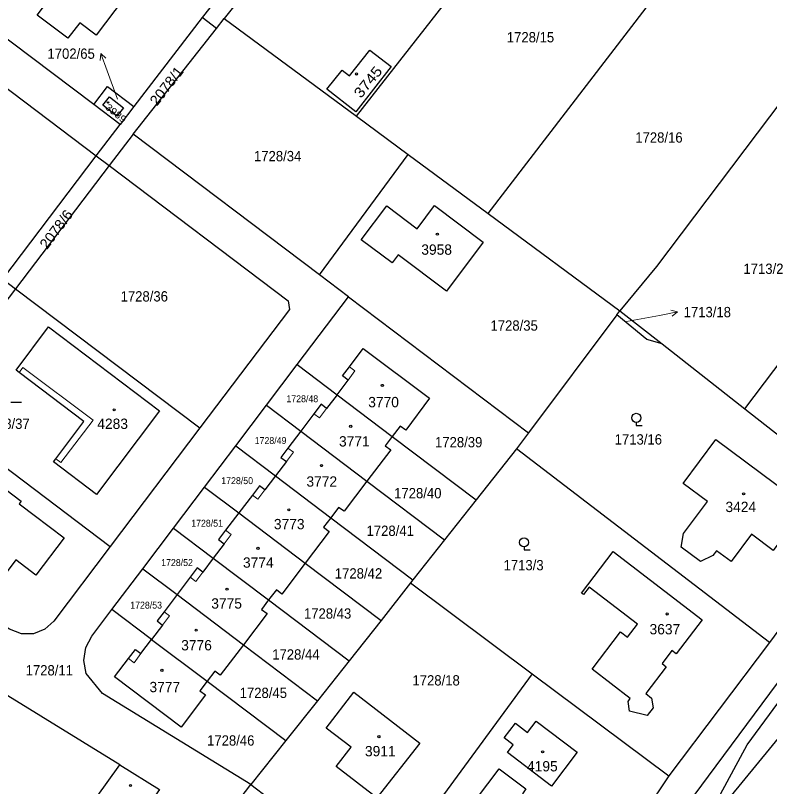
# Model space of a CAD drawing. Extents: x -679733 to -673243, y -1075091 to -1066557.
# Drawn here: x -677106.6 to -676982.3, y -1072174.7 to -1072047.5 of the extents above; entities that cross this region are included whole.
import ezdxf
from ezdxf.enums import TextEntityAlignment as Align

# ---------------------------------------------------------------- set-up
doc = ezdxf.new("R2010")
doc.units = 0
doc.header["$LTSCALE"] = 0.68
for name, color, linetype, lineweight in [('1', 7, 'Continuous', 25), ('3', 7, 'Continuous', 25), ('4', 7, 'Continuous', 13), ('5', 7, 'Continuous', 25), ('7', 7, 'Continuous', 13)]:
    doc.layers.add(name, color=color, linetype=linetype, lineweight=lineweight)
doc.layers.add('2', color=7, linetype='Continuous')

msp = doc.modelspace()

# ---------------------------------------------------------------- linework, layer by layer
at = {"layer": '1'}
for p, q in [((-677074.58, -1072046.3), (-677075.82, -1072047.9)), ((-677073.48, -1072049.71), (-677072.18, -1072048.07)), ((-677093.28, -1072070.69), (-677091.14, -1072072.31)), ((-677056.5, -1072090.33), (-677041.85, -1072070.46)), ((-677028.68, -1072080.19), (-677006.95, -1072096.23)), ((-677108.7, -1072091), (-677106.59, -1072092.6)), ((-677051.71, -1072093.95), (-677022.03, -1072116.37)), ((-677007.46, -1072096.91), (-677006.95, -1072096.23)), ((-677006.95, -1072096.23), (-677000, -1072101.69)), ((-677060.16, -1072105.11), (-677053.59, -1072110.07)), ((-677053.59, -1072110.07), (-677044.48, -1072116.96)), ((-677065.22, -1072111.81), (-677059.57, -1072116.08)), ((-676986.37, -1072112.39), (-676965.77, -1072128.57)), ((-677059.57, -1072116.08), (-677048.65, -1072124.33)), ((-677044.48, -1072116.96), (-677030.64, -1072127.41)), ((-677070.29, -1072118.51), (-677063.73, -1072123.47)), ((-677048.65, -1072124.33), (-677035.85, -1072134)), ((-677075.42, -1072125.29), (-677069.77, -1072129.56)), ((-677069.77, -1072129.56), (-677058.83, -1072137.82)), ((-677054.62, -1072130.36), (-677041.06, -1072140.6)), ((-677080.55, -1072132.07), (-677073.99, -1072137.02)), ((-677073.99, -1072137.02), (-677064.87, -1072143.91)), ((-677085.62, -1072138.77), (-677079.97, -1072143.03)), ((-677084.15, -1072150.41), (-677090.69, -1072145.47)), ((-677084.15, -1072150.41), (-677075.01, -1072157.31)), ((-677069.03, -1072151.3), (-677056.82, -1072160.52)), ((-677021.42, -1072156.06), (-677046.63, -1072190.51)), ((-677089.42, -1072171.09), (-677082.85, -1072175.14))]:
    msp.add_line(p, q, dxfattribs=at)
for points in [[(-677017.03, -1072021.51), (-677038.79, -1072006.32), (-677072.18, -1072048.07), (-677050.4, -1072064.16)], [(-677097.95, -1072051.28), (-677103.02, -1072047.53), (-677101.13, -1072044.95), (-677103.7, -1072043.07), (-677097.58, -1072034.86), (-677087.13, -1072042.64), (-677093.28, -1072050.82), (-677096, -1072048.77)], [(-677048.19, -1072053.29), (-677044.66, -1072055.95), (-677050.49, -1072063.44), (-677055.26, -1072059.73), (-677052.75, -1072056.56), (-677051.54, -1072057.51)], [(-677088.8, -1072062.76), (-677089.88, -1072064.14), (-677092.18, -1072062.32), (-677091.11, -1072060.96)], [(-677045.39, -1072078.94), (-677040.4, -1072082.71), (-677037.54, -1072078.89), (-677029.5, -1072084.92), (-677035.55, -1072092.98), (-677043.51, -1072087.01), (-677044.5, -1072088.35), (-677049.58, -1072084.54)], [(-677106, -1072106.42), (-677106.51, -1072106.03), (-677101.15, -1072098.9), (-677082.84, -1072112.73), (-677093.22, -1072126.53), (-677100.34, -1072121.12), (-677099.95, -1072120.62), (-677095.34, -1072114.51)], [(-676991.02, -1072135.79), (-676991.65, -1072136.57), (-676993.63, -1072137.58), (-676996.84, -1072135.18), (-676996.46, -1072132.95), (-676992.52, -1072127.67), (-676996.51, -1072124.7), (-676991.14, -1072117.47), (-676976.27, -1072128.51), (-676981.66, -1072135.77), (-676985.27, -1072133.08), (-676988.61, -1072137.57)], [(-677117.05, -1072129.2), (-677112.13, -1072122.73), (-677105.66, -1072127.62), (-677106, -1072128.08), (-677098.59, -1072133.68), (-677103.25, -1072139.81), (-677106.53, -1072137.27), (-677109.37, -1072141), (-677112.1, -1072138.93), (-677112.28, -1072139.16), (-677114.97, -1072137.06), (-677114.8, -1072136.83), (-677117.35, -1072134.96), (-677119.89, -1072133.07)], [(-677002.69, -1072159.33), (-677001.72, -1072160.09), (-677001.48, -1072161.67), (-677002.44, -1072162.96), (-677005.38, -1072162.26), (-677005.56, -1072160.64), (-677005.25, -1072160.16), (-677011.53, -1072155.33), (-677006.85, -1072149.18), (-677005.68, -1072150.05), (-677004.06, -1072147.9), (-677012.04, -1072141.82), (-677012.95, -1072143.02), (-677013.28, -1072142.78), (-677008.04, -1072135.92), (-676993.39, -1072147.17), (-676997.65, -1072152.79), (-676998.37, -1072152.26), (-676999.99, -1072154.4), (-676999.31, -1072154.94)], [(-677047.03, -1072176.53), (-677053.73, -1072171.35), (-677051.28, -1072168.19), (-677055.37, -1072165.02), (-677050.84, -1072159.13), (-677039.96, -1072167.5)], [(-677014.01, -1072169.02), (-677018.21, -1072174.6), (-677025.47, -1072169.08), (-677024.53, -1072167.77), (-677026.01, -1072166.65), (-677024.16, -1072164.22), (-677022.19, -1072165.76), (-677020.75, -1072163.91)], [(-677022.43, -1072175.06), (-677023.03, -1072175.85), (-677013.34, -1072183.15), (-677017.74, -1072189.03), (-677020.94, -1072186.65), (-677024.75, -1072191.65), (-677029.79, -1072187.85), (-677030, -1072188.09), (-677035.87, -1072183.69), (-677026.86, -1072171.73)]]:
    msp.add_lwpolyline(points, close=True, dxfattribs=at)
for points in [[(-677050.4, -1072064.16), (-677041.85, -1072070.46), (-677028.68, -1072080.19), (-676995.7, -1072037.23), (-677017.03, -1072021.51)], [(-677143.01, -1072065.09), (-677128.23, -1072045.55), (-677126.83, -1072045.35), (-677093.28, -1072070.69), (-677089.36, -1072065.52), (-677093.71, -1072062.23), (-677124.11, -1072039.27), (-677128.9, -1072035.65), (-677137.65, -1072047.21), (-677142.72, -1072053.91), (-677147.79, -1072060.61), (-677152.92, -1072067.39), (-677158.04, -1072074.17)], [(-677075.82, -1072047.9), (-677087.1, -1072062.55), (-677089.36, -1072065.52)], [(-677087.2, -1072067.14), (-677073.48, -1072049.71), (-677075.82, -1072047.9)], [(-677003.56, -1072188.05), (-676937.07, -1072098.47), (-676924.77, -1072082.25), (-676901.08, -1072050.53), (-676900.33, -1072051.15)], [(-676973.98, -1072053.28), (-677000.89, -1072088.91), (-677006.95, -1072096.23)], [(-677093.71, -1072062.23), (-677091.45, -1072059.24), (-677087.1, -1072062.55)], [(-677143.01, -1072065.09), (-677108.7, -1072091), (-677093.28, -1072070.69)], [(-677067.77, -1072174.34), (-677092.23, -1072159.33), (-677094.94, -1072156.01), (-677095.33, -1072153.89), (-677095.01, -1072151.77), (-677094.01, -1072149.86), (-677090.69, -1072145.47), (-677085.62, -1072138.77), (-677080.55, -1072132.07), (-677075.42, -1072125.29), (-677070.29, -1072118.51), (-677065.22, -1072111.81), (-677060.16, -1072105.11), (-677051.71, -1072093.95), (-677056.5, -1072090.33), (-677087.2, -1072067.14), (-677091.14, -1072072.31)], [(-677091.14, -1072072.31), (-677106.59, -1072092.6), (-677076.2, -1072115.55)], [(-677091.14, -1072072.31), (-677061.62, -1072094.61), (-677061.42, -1072096.01), (-677076.2, -1072115.55), (-677090.98, -1072135.09)], [(-676926.11, -1072076.11), (-676932.42, -1072084.22), (-676965.77, -1072128.57), (-676982.28, -1072150.91), (-676998.86, -1072172.9), (-677002.77, -1072178.71)], [(-677000, -1072101.69), (-676986.37, -1072112.39), (-676968.77, -1072089.16)], [(-676996.56, -1072187.43), (-676985.94, -1072167.77), (-676927.29, -1072088.05)], [(-676924.4, -1072090.21), (-676960.77, -1072142.26), (-676990.83, -1072178.91), (-676996.56, -1072187.43)], [(-677106.59, -1072092.6), (-677121.44, -1072112.08), (-677090.98, -1072135.09)], [(-677007.46, -1072096.91), (-677022.03, -1072116.37), (-677023.98, -1072118.97)], [(-677000, -1072101.69), (-677002.48, -1072100.95), (-677007.46, -1072096.91)], [(-677053.59, -1072110.07), (-677051.77, -1072107.67), (-677052.66, -1072106.97), (-677051.53, -1072105.46), (-677049.26, -1072102.44), (-677038.33, -1072110.66), (-677042.25, -1072115.93), (-677043.19, -1072115.25), (-677044.48, -1072116.96)], [(-677053.59, -1072110.07), (-677055.33, -1072112.36), (-677056.2, -1072111.65), (-677057.41, -1072113.21), (-677059.57, -1072116.08)], [(-677059.57, -1072116.08), (-677061.68, -1072118.87), (-677062.83, -1072120.4), (-677061.92, -1072121.08), (-677063.73, -1072123.47), (-677054.62, -1072130.36)], [(-677044.48, -1072116.96), (-677045.64, -1072118.5), (-677044.74, -1072119.16), (-677048.65, -1072124.33)], [(-676982.28, -1072150.91), (-677023.98, -1072118.97), (-677030.64, -1072127.41), (-677035.85, -1072134), (-677041.06, -1072140.6), (-677041.46, -1072141.11)], [(-677063.73, -1072123.47), (-677065.47, -1072125.76), (-677066.35, -1072125.09), (-677067.52, -1072126.63), (-677069.77, -1072129.56)], [(-677048.65, -1072124.33), (-677052.4, -1072129.28), (-677053.32, -1072128.66), (-677054.62, -1072130.36)], [(-677069.77, -1072129.56), (-677071.97, -1072132.43), (-677073.12, -1072133.93), (-677072.22, -1072134.63), (-677073.99, -1072137.02)], [(-677090.98, -1072135.09), (-677100.28, -1072147.39), (-677101.76, -1072148.73), (-677103.62, -1072149.47), (-677105.62, -1072149.48), (-677107.58, -1072148.73), (-677119.65, -1072141.33), (-677126.55, -1072136.93), (-677133.31, -1072132.31), (-677135.61, -1072130.68)], [(-677054.62, -1072130.36), (-677055.79, -1072131.89), (-677054.9, -1072132.6), (-677058.83, -1072137.82), (-677046.33, -1072147.27)], [(-677073.99, -1072137.02), (-677075.72, -1072139.33), (-677076.62, -1072138.63), (-677077.78, -1072140.15), (-677079.97, -1072143.03), (-677069.03, -1072151.3)], [(-677058.83, -1072137.82), (-677062.68, -1072142.93), (-677063.59, -1072142.24), (-677064.87, -1072143.91), (-677051.61, -1072153.93)], [(-677041.46, -1072141.11), (-677046.33, -1072147.27), (-677051.61, -1072153.93), (-677056.82, -1072160.52)], [(-677041.46, -1072141.11), (-677021.42, -1072156.06), (-676998.86, -1072172.9)], [(-677079.97, -1072143.03), (-677082.11, -1072145.84), (-677083.26, -1072147.35), (-677082.36, -1072148.06), (-677084.15, -1072150.41)], [(-677064.87, -1072143.91), (-677066.05, -1072145.46), (-677065.13, -1072146.16), (-677069.03, -1072151.3)], [(-677075.01, -1072157.31), (-677076.2, -1072158.87), (-677075.29, -1072159.56), (-677079.26, -1072164.87), (-677090.26, -1072156.6), (-677087.98, -1072153.57), (-677086.83, -1072152.06), (-677085.91, -1072152.75), (-677084.15, -1072150.41)], [(-677069.03, -1072151.3), (-677072.83, -1072156.32), (-677073.73, -1072155.63), (-677075.01, -1072157.31), (-677062.04, -1072167.1)], [(-677082.85, -1072175.14), (-677086.97, -1072181.02), (-677093.32, -1072176.54), (-677089.42, -1072171.09), (-677108.59, -1072159.26), (-677131.37, -1072188.86), (-677097.67, -1072213.39)], [(-677056.82, -1072160.52), (-677062.04, -1072167.1), (-677067.77, -1072174.34), (-677046.63, -1072190.51)], [(-677070.68, -1072177.99), (-677068.7, -1072175.5), (-677067.77, -1072174.34)]]:
    msp.add_lwpolyline(points, dxfattribs=at)
at = {"layer": '3'}
msp.add_line((-677107.383, -1072111.3), (-677105.633, -1072111.3), dxfattribs=at)
for points in [[(-677004.25, -1072114.642), (-677004.25, -1072115.14), (-677003.249, -1072115.14)], [(-677022.75, -1072135.172), (-677022.75, -1072135.67), (-677021.749, -1072135.67)]]:
    msp.add_lwpolyline(points, dxfattribs=at)
for centre in [(-677004.2493, -1072113.8909), (-677022.7493, -1072134.4209)]:
    msp.add_circle(centre, 0.75, dxfattribs=at)
at = {"layer": '4'}
for p, q in [((-677050.63, -1072106.16), (-677051.53, -1072105.46)), ((-677051.77, -1072107.67), (-677050.63, -1072106.16)), ((-677057.41, -1072113.21), (-677056.47, -1072113.87)), ((-677056.47, -1072113.87), (-677055.33, -1072112.36)), ((-677061.92, -1072121.08), (-677060.77, -1072119.57)), ((-677060.77, -1072119.57), (-677061.68, -1072118.87)), ((-677066.62, -1072127.27), (-677065.47, -1072125.76)), ((-677067.52, -1072126.63), (-677066.62, -1072127.27)), ((-677071.06, -1072133.11), (-677071.97, -1072132.43)), ((-677072.22, -1072134.63), (-677071.06, -1072133.11)), ((-677076.86, -1072140.84), (-677075.72, -1072139.33)), ((-677077.78, -1072140.15), (-677076.86, -1072140.84)), ((-677081.23, -1072146.52), (-677082.11, -1072145.84)), ((-677082.36, -1072148.06), (-677081.23, -1072146.52)), ((-677087.05, -1072154.27), (-677085.91, -1072152.75)), ((-677087.98, -1072153.57), (-677087.05, -1072154.27))]:
    msp.add_line(p, q, dxfattribs=at)
msp.add_lwpolyline([(-677106, -1072106.42), (-677105.37, -1072105.59), (-677093.79, -1072114.28), (-677099.11, -1072121.25), (-677099.95, -1072120.62)], dxfattribs=at)
at = {"layer": '5'}
for centre, radius in [((-677050.3868, -1072057.1992), 0.175), ((-677091.3446, -1072061.8894), 0.1172), ((-677037.0468, -1072083.6092), 0.175), ((-677046.1068, -1072108.5392), 0.175), ((-677090.3168, -1072112.5692), 0.175), ((-677051.3368, -1072115.2892), 0.175), ((-677056.1568, -1072121.7592), 0.175), ((-676986.5468, -1072126.4092), 0.175), ((-677061.5268, -1072129.0592), 0.175), ((-677066.6168, -1072135.3892), 0.175), ((-677071.7168, -1072142.1392), 0.175), ((-676999.1568, -1072146.2192), 0.175), ((-677076.8068, -1072148.8892), 0.175), ((-677082.4568, -1072155.4992), 0.175), ((-677046.6768, -1072166.4492), 0.175), ((-677019.6868, -1072168.9392), 0.175), ((-677087.6468, -1072174.4892), 0.175)]:
    msp.add_circle(centre, radius, dxfattribs=at)
at = {"layer": '7'}
for p, q in [((-677092.516, -1072053.85), (-677092.644, -1072054.962)), ((-676997.444, -1072096.427), (-676998.523, -1072096.127))]:
    msp.add_line(p, q, dxfattribs=at)
for points in [[(-677089.78, -1072061.36), (-677091.49, -1072056.67), (-677092.516, -1072053.85), (-677091.703, -1072054.62)], [(-677005.85, -1072098.01), (-677000.39, -1072097), (-676997.444, -1072096.427), (-676998.332, -1072097.11)]]:
    msp.add_lwpolyline(points, dxfattribs=at)

# ---------------------------------------------------------------- texts
at = {"layer": '2', "width": 0.95}
for s, height, p in [('1728/15', 1.7, (-677025.59, -1072051.989)), ('1728/16', 1.7, (-677004.41, -1072068.519)), ('1728/34', 1.7, (-677067.28, -1072071.59)), ('1713/2', 1.7, (-676986.58, -1072090.16)), ('1728/36', 1.7, (-677089.27, -1072094.71)), ('1713/18', 1.7, (-676996.44, -1072097.3)), ('1728/35', 1.7, (-677028.28, -1072099.519)), ('1728/48', 1.14, (-677061.93, -1072111.31)), ('1728/37', 1.7, (-677112.06, -1072115.71)), ('1728/49', 1.14, (-677067.16, -1072118.199)), ('1728/39', 1.7, (-677037.43, -1072118.749)), ('1713/16', 1.7, (-677007.81, -1072118.29)), ('1728/50', 1.14, (-677072.67, -1072124.81)), ('1728/40', 1.7, (-677044.17, -1072127.15)), ('1728/51', 1.14, (-677077.63, -1072131.83)), ('1728/41', 1.7, (-677048.72, -1072133.35)), ('1728/52', 1.14, (-677082.58, -1072138.31)), ('1713/3', 1.7, (-677026.13, -1072139.019)), ('1728/42', 1.7, (-677053.95, -1072140.38)), ('1728/53', 1.14, (-677087.68, -1072145.33)), ('1728/43', 1.7, (-677059.04, -1072146.989)), ('1728/44', 1.7, (-677064.27, -1072153.739)), ('1728/11', 1.7, (-677104.93, -1072156.35)), ('1728/18', 1.7, (-677041.15, -1072158.009)), ('1728/45', 1.7, (-677069.64, -1072160.07)), ('1728/46', 1.7, (-677075.01, -1072167.92))]:
    msp.add_text(s, height=height, dxfattribs=at).set_placement(p)
msp.add_text('1702/65', height=1.7, dxfattribs=at).set_placement((-677093.52, -1072054.7), align=Align.RIGHT)
at = {"layer": '2'}
for s, rotation, width, p in [('2078/1', 52, 1.05, (-677083.27, -1072062.573)), ('3745', 51, 1.15, (-677049.649, -1072061.314)), ('2078/6', 53, 1.05, (-677101.401, -1072086.231))]:
    msp.add_text(s, height=1.7, rotation=rotation, dxfattribs=dict(at, width=width)).set_placement(p)
at = {"layer": '2', "width": 1.15}
msp.add_text('3989', height=1.14, rotation=321, dxfattribs=at).set_placement((-677090.3992, -1072064.1058), align=Align.CENTER)
at = {"layer": '2'}
for s, p in [('3958', (-677039.69, -1072086.999)), ('3770', (-677048.44, -1072112.14)), ('3771', (-677053.26, -1072118.61)), ('3772', (-677058.63, -1072125.229)), ('3424', (-676989.54, -1072129.42)), ('3773', (-677064, -1072132.249)), ('3774', (-677069.09, -1072138.59)), ('3775', (-677074.32, -1072145.33)), ('3637', (-677002.06, -1072149.58)), ('3776', (-677079.28, -1072152.22)), ('3777', (-677084.51, -1072159.11)), ('3911', (-677048.98, -1072169.68))]:
    msp.add_text(s, height=1.7, dxfattribs=at).set_placement(p)
for s, p in [('4283', (-677090.58, -1072115.71)), ('4195', (-677019.73, -1072172.17))]:
    msp.add_text(s, height=1.7, dxfattribs=at).set_placement(p, align=Align.CENTER)

doc.saveas('drawing.dxf')
